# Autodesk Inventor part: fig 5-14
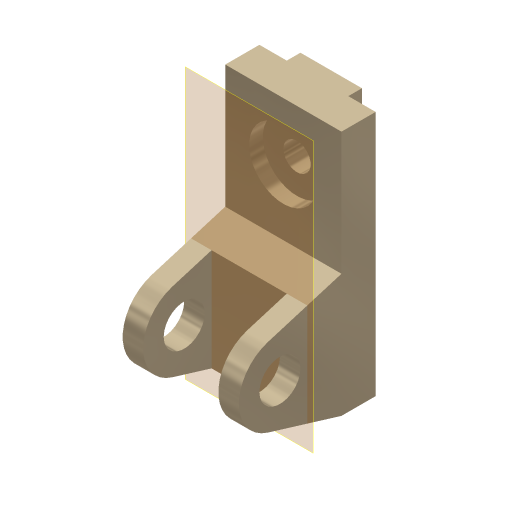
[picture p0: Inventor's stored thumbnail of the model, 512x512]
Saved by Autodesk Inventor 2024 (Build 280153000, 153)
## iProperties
Shininess: 65.0
Angle Display Precision: 2
Document Length Units: 11269
Document Angle Units: 11279
Document Time Units: 11290
Document Mass Units: 11283
Document Length Units Precision: 3
Document Angle Units Precision: 2
Compacted: False
Created: 2001-11
Part Number: fig 5-14
Document SubType Name: Modeling
Designer: Renu Muthoo
Density: 1 g/cm^3
Material: Generic
Appearance: Metal-Titanium (Polished)
Density: 0.0
Volumn: 0.0
Area: 0.0
PropertySet Name: Model Information
Control State: 0
Master: False
Checked Out: False
Author: Renu Muthoo
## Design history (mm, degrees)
sketch "Sketch2"
  geometry: L1 (33.257, 104.664)-(33.257, -75.336); L2 (33.257, -75.336)-(8.257, -75.336); L3 (8.257, -75.336)-(-45.451, -59.045); L4 (-45.451, -1.628)-(8.257, 14.664); L5 (8.257, 14.664)-(8.257, 104.664); L6 (8.257, 104.664)-(33.257, 104.664); C1 r 15 at (-36.743, -30.336); A1 r 30 centre (-36.743, -30.336) between (-45.451, -1.628) and (-45.451, -59.045)
  constraints: 12 end point, 2 centre point, 2 equal length, 2 parallel, 2 point on circle, 2 tangent, 1 coincident, 1 perpendicular, 1 vertical
  dimensions: "d0" = 180 distance of L1.start L1.end; "d1" = 30 radius of A1; "d2" = 25 distance of L5.end L1.start; "d3" = 45 distance from line of L2 A1.centre; "d4" = 70 distance from line of L1 A1.centre; "d5" = 30 diameter of C1
extrude "Extrusion1" new body sketch "Sketch2" distance "d6" = 85; taper "d7" = 0 deg
workplane "Work Plane1"
sketch "Sketch3"
  geometry: L1 (15, 62.364)-(70, 62.364); L2 (70, 62.364)-(70, -52.386); L3 (70, -52.386)-(15, -52.386); L4 (15, -52.386)-(15, 62.364); L5 (0, -45)-(0, -28.708) reference
  constraints: 8 end point, 2 parallel, 1 horizontal, 1 perpendicular
  dimensions: "d8" = 55 distance of L1.start L1.end; "d9" = 15 distance between parallel lines of L5 L4
extrude "Extrusion2" cut sketch "Sketch3" distance "d10" = 50; taper "d11" = 0 deg
sketch "Sketch4"
  geometry: L1 (0, 25)-(85, 25) reference; L2 (0, 0)-(0, 25) reference; L3 (20, 25)-(65, 25); L4 (65, 25)-(65, 35); L5 (65, 35)-(20, 35); L6 (20, 35)-(20, 25)
  constraints: 8 end point, 2 parallel, 1 horizontal, 1 perpendicular, 1 point on line
  dimensions: "d12" = 45 distance of L4.end L5.end; "d13" = 10 distance of L3.end L4.end; "d14" = 20 distance between parallel lines of L2 L6
extrude "Extrusion3" join sketch "Sketch4" stored distance "d15" = 50; taper "d16" = 0 deg
sketch "Sketch5"
  geometry: L1 (85, 0)-(85, 90) reference; L2 (0, 90)-(85, 90) reference; 1 further point
  dimensions: "d17" = 42 distance from line of L2 point (42.5, 48); "d18" = 42.5 distance from line of L1 point (42.5, 48)
hole "Hole1" sketch "Sketch5" diameter "d19" = 20; stored, may be unused: countersink angle "d23" = 82 deg, drill point angle "d25" = 118 deg; dims "d20" = 6, "d21" = 50, "d22" = 10, "d24" = 8
workplane "Work Plane6"
body "Solid1"
node "Sketch1"
other parameters: "d26" = 0
